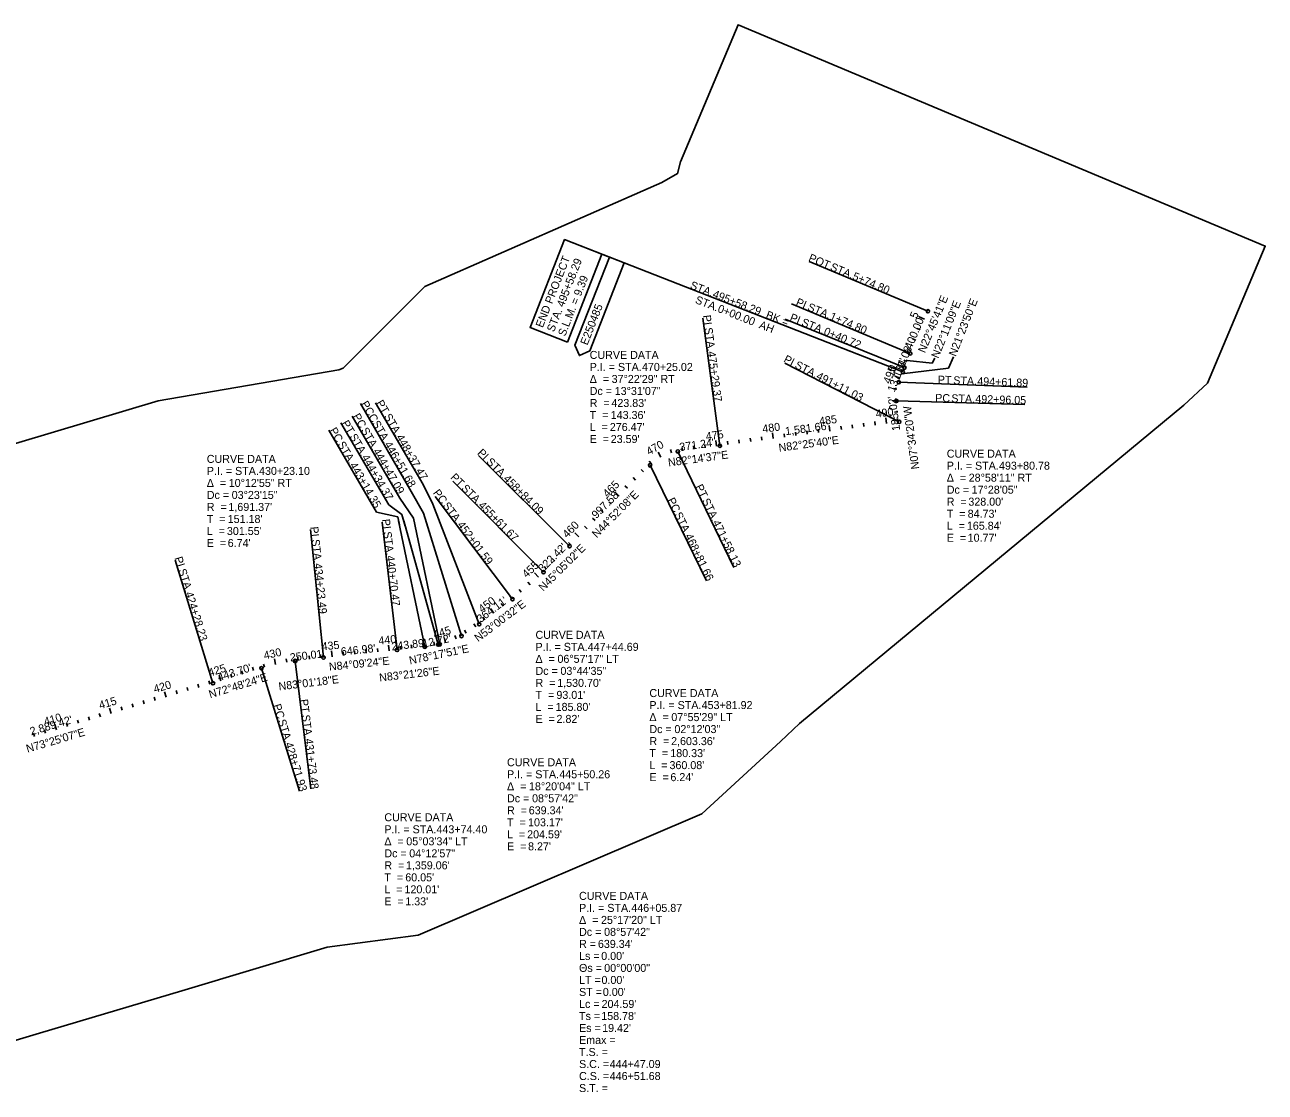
# Model space of a CAD drawing. Extents: x 187058 to 230449, y 263308 to 297406.
# Drawn here: x 219600 to 230449, y 288075 to 297406 of the extents above; entities that cross this region are included whole.
import ezdxf

# ---------------------------------------------------------------- set-up
doc = ezdxf.new("R2010")
doc.units = 0
for name, color, linetype in [('BR_X_Gen_Approach_Slab', 7, 'Continuous'), ('BR_X_SV_Deck_Top', 7, 'Continuous'), ('PV_X_Curb', 7, 'Continuous'), ('PV_X_Walk', 7, 'Continuous'), ('RD_X_GR_Lt', 7, 'Continuous'), ('SH_Named_Boundary', 7, 'Continuous')]:
    doc.layers.add(name, color=color, linetype=linetype)

msp = doc.modelspace()

# ---------------------------------------------------------------- linework, layer by layer
at = {"layer": 'BR_X_SV_Deck_Top'}
for p, q in [((227470, 294833), (227424, 294852)), ((227393, 294648), (227365, 294660)), ((227431, 294740), (227404, 294752)), ((227354, 294556), (227326, 294568)), ((227316, 294463), (227288, 294475)), ((227257, 294316), (227211, 294335)), ((227279, 294371), (227232, 294389)), ((227226, 294222), (227197, 294227)), ((227223, 294122), (227193, 294118)), ((227236, 294023), (227207, 294019)), ((226642, 293854), (226636, 293904)), ((226742, 293867), (226738, 293897)), ((226841, 293880), (226837, 293910)), ((226940, 293894), (226936, 293923)), ((227039, 293907), (227035, 293937)), ((227138, 293920), (227131, 293970)), ((227237, 293933), (227233, 293963)), ((225949, 293762), (225945, 293792)), ((226048, 293775), (226044, 293805)), ((226147, 293788), (226140, 293838)), ((226246, 293801), (226242, 293831)), ((226345, 293815), (226341, 293844)), ((226444, 293828), (226440, 293857)), ((226543, 293841), (226539, 293871)), ((225256, 293664), (225247, 293693)), ((225354, 293682), (225350, 293711)), ((225453, 293695), (225449, 293725)), ((225552, 293709), (225548, 293738)), ((225651, 293722), (225644, 293772)), ((225750, 293736), (225746, 293765)), ((225849, 293749), (225845, 293778)), ((225082, 293568), (225062, 293590)), ((225163, 293626), (225139, 293670)), ((225012, 293497), (224990, 293518)), ((224871, 293356), (224849, 293377)), ((224941, 293426), (224920, 293448)), ((224800, 293285), (224765, 293320)), ((224659, 293143), (224638, 293164)), ((224729, 293214), (224708, 293235)), ((224588, 293072), (224567, 293093)), ((224447, 292930), (224412, 292966)), ((224518, 293001), (224497, 293022)), ((224306, 292789), (224285, 292810)), ((224377, 292859), (224355, 292881)), ((224235, 292718), (224214, 292739)), ((224093, 292577), (224059, 292614)), ((224164, 292648), (224143, 292669)), ((224019, 292510), (223999, 292532)), ((223864, 292384), (223846, 292408)), ((223943, 292445), (223924, 292469)), ((223704, 292263), (223674, 292303)), ((223784, 292324), (223766, 292348)), ((223544, 292143), (223527, 292168)), ((223625, 292203), (223606, 292227)), ((223281, 292003), (223267, 292051)), ((223374, 292039), (223361, 292066)), ((223461, 292088), (223445, 292113)), ((222587, 291913), (222584, 291943)), ((222687, 291923), (222684, 291953)), ((222786, 291933), (222781, 291983)), ((222886, 291944), (222882, 291974)), ((222985, 291956), (222981, 291985)), ((223084, 291967), (223081, 291997)), ((223183, 291981), (223178, 292011)), ((221794, 291814), (221783, 291863)), ((221892, 291834), (221887, 291863)), ((221991, 291848), (221987, 291877)), ((222090, 291860), (222086, 291889)), ((222189, 291872), (222186, 291902)), ((222289, 291882), (222284, 291932)), ((222388, 291893), (222385, 291923)), ((222488, 291903), (222485, 291933)), ((221410, 291701), (221401, 291730)), ((221506, 291730), (221497, 291759)), ((221601, 291760), (221592, 291789)), ((221697, 291789), (221689, 291818)), ((221123, 291614), (221115, 291642)), ((221219, 291642), (221211, 291671)), ((221315, 291671), (221300, 291719)), ((220740, 291499), (220731, 291528)), ((220836, 291528), (220821, 291576)), ((220932, 291556), (220923, 291585)), ((221027, 291585), (221019, 291614)), ((220357, 291385), (220342, 291433)), ((220452, 291414), (220444, 291443)), ((220548, 291442), (220540, 291471)), ((220644, 291471), (220635, 291500)), ((219877, 291243), (219863, 291290)), ((219973, 291271), (219965, 291300)), ((220069, 291300), (220060, 291328)), ((220165, 291328), (220156, 291357)), ((220261, 291357), (220252, 291385)), ((219686, 291185), (219677, 291214)), ((219781, 291214), (219773, 291243))]:
    msp.add_line(p, q, dxfattribs=at)
at = {"layer": 'PV_X_Walk'}
for p, q in [((227279, 294371), (224322, 295529)), ((227499, 294902), (226462, 295337)), ((227279, 294371), (225952, 294891)), ((227344, 294533), (226307, 294968)), ((225680, 293726), (225532, 294841)), ((227294, 294409), (226252, 294833)), ((227248, 293935), (226248, 294449)), ((227319, 294471), (227536, 294448)), ((227536, 294448), (227559, 294493)), ((227679, 294405), (227724, 294503)), ((227272, 294354), (227679, 294405)), ((227244, 294281), (228368, 294239)), ((227224, 294118), (228348, 294088)), ((222535, 294094), (222979, 293326)), ((222668, 294102), (223085, 293387)), ((222365, 293926), (222784, 293209)), ((222463, 293986), (222881, 293269)), ((222258, 293863), (222675, 293146)), ((224365, 292848), (223568, 293642)), ((225312, 293676), (225801, 292663)), ((225069, 293555), (225562, 292544)), ((223085, 293387), (223168, 293215)), ((224137, 292620), (223343, 293417)), ((222881, 293269), (223001, 293092)), ((222979, 293326), (223086, 293137)), ((223865, 292385), (223189, 293283)), ((222675, 293146), (222862, 293106)), ((222784, 293209), (222899, 293126)), ((223420, 292063), (223086, 293137)), ((223575, 292166), (223168, 293215)), ((222856, 291941), (222726, 293058)), ((222862, 293106), (222877, 293036)), ((223099, 291969), (222870, 293070)), ((222899, 293126), (222928, 293022)), ((223217, 291988), (222914, 293071)), ((223229, 291990), (223001, 293092)), ((222213, 291875), (222098, 292994)), ((221246, 291650), (220914, 292725)), ((221965, 291844), (222101, 290728)), ((221670, 291781), (222003, 290707))]:
    msp.add_line(p, q, dxfattribs=at)
msp.add_lwpolyline([(224346, 294631), (224648, 295402), (224322, 295529), (224020, 294759)], close=True, dxfattribs=at)
msp.add_lwpolyline([(224713, 295376), (224411, 294606), (224451, 294515), (224541, 294555), (224843, 295325), (224648, 295402)], dxfattribs=at)
for centre in [(227499, 294902), (227344, 294533), (227279, 294371), (227294, 294409), (227244, 294281), (227224, 294118), (227248, 293935), (225312, 293676), (225680, 293726), (225069, 293555), (224365, 292848), (224137, 292620), (223865, 292385), (223575, 292166), (223420, 292063), (222856, 291941), (223099, 291969), (223217, 291988), (223229, 291990), (221965, 291844), (222213, 291875), (221670, 291781), (221246, 291650)]:
    msp.add_circle(centre, 15, dxfattribs=at)
at = {"layer": 'SH_Named_Boundary'}
msp.add_lwpolyline([(217055, 293010), (218483, 288219), (219728, 288590), (220974, 288961), (222245, 289342), (223041, 289446), (225522, 290507), (226211, 291141), (226377, 291297), (229737, 294082), (229946, 294273), (230449, 295471), (225839, 297406), (225336, 296207), (225310, 296106), (225171, 296027), (223099, 295119), (222384, 294404), (222347, 294389), (220767, 294119), (219547, 293753), (218301, 293382)], close=True, dxfattribs=at)

# ---------------------------------------------------------------- texts
at = {"layer": 'BR_X_Gen_Approach_Slab'}
for s, rotation, p in [("400.00'", 67.2385, (227356, 294564)), ("134.08'", 67.814, (227255, 294316)), ("137.11'", 68.6028, (227207, 294190)), ("185.02'", 97.5724, (227257, 293861)), ("1,581.66'", 7.5724, (226255, 293818)), ("371.24'", 7.7564, (225331, 293680)), ("997.58'", 45.1312, (224599, 293084)), ("322.42'", 44.9162, (224132, 292617)), ("364.11'", 36.9912, (223586, 292175)), ("12.72'", 11.7024, (223087, 291961)), ("250.01'", 6.9782, (221923, 291840)), ("646.98'", 5.8434, (222368, 291892)), ("243.89'", 6.6427, (222811, 291936)), ("443.70'", 17.1934, (221298, 291667)), ("2,889.42'", 16.5814, (219657, 291193))]:
    msp.add_text(s, height=70, rotation=rotation, dxfattribs=at).set_placement(p)
at = {"layer": 'BR_X_SV_Deck_Top'}
for s, rotation, p in [('5', 67.2385, (227402, 294832)), ('495', 68.6028, (227169, 294262)), ('0', 68.6028, (227210, 294368)), ('490', 7.5724, (227047, 293971)), ('480', 7.5724, (226056, 293839)), ('485', 7.5724, (226552, 293905)), ('475', 7.7564, (225561, 293773)), ('470', 29.1338, (225060, 293640)), ('465', 45.1312, (224697, 293270)), ('460', 45.1312, (224344, 292915)), ('455', 43.5588, (223990, 292566)), ('450', 36.9912, (223600, 292263)), ('440', 5.8434, (222697, 291987)), ('445', 16.444, (223184, 292040)), ('430', 12.8549, (221698, 291857)), ('435', 5.8434, (222200, 291936)), ('425', 17.1934, (221217, 291707)), ('420', 16.5814, (220738, 291564)), ('415', 16.5814, (220260, 291422)), ('410', 16.5814, (219779, 291279))]:
    msp.add_text(s, height=70, rotation=rotation, dxfattribs=at).set_placement(p)
at = {"layer": 'PV_X_Curb'}
for s, p in [('CURVE DATA', (224541, 294485)), ('P.I. = STA. ', (224541, 294380)), ('470+25.02', (224998, 294380)), ('Δ  = ', (224541, 294275)), ('37°22\'29" RT', (224733, 294275)), ('Dc = ', (224541, 294170)), ('13°31\'07"', (224760, 294170)), ('R  = ', (224541, 294065)), ("423.83'", (224731, 294065)), ('T  = ', (224541, 293960)), ("143.36'", (224725, 293960)), ('L  = ', (224541, 293855)), ("276.47'", (224717, 293855)), ('E  = ', (224541, 293750)), ("23.59'", (224725, 293750)), ('CURVE DATA', (227664, 293622)), ('CURVE DATA', (221192, 293576)), ('P.I. = STA. ', (227664, 293517)), ('493+80.78', (228121, 293517)), ('P.I. = STA. ', (221192, 293471)), ('430+23.10', (221649, 293471)), ('Δ  = ', (227664, 293412)), ('28°58\'11" RT', (227856, 293412)), ('Δ  = ', (221192, 293366)), ('10°12\'55" RT', (221384, 293366)), ('Dc = ', (227664, 293307)), ('17°28\'05"', (227882, 293307)), ('Dc = ', (221192, 293261)), ('03°23\'15"', (221410, 293261)), ('R  = ', (227664, 293202)), ("328.00'", (227853, 293202)), ('R  = ', (221192, 293156)), ("1,691.37'", (221381, 293156)), ('T  = ', (227664, 293097)), ("84.73'", (227847, 293097)), ('T  = ', (221192, 293051)), ("151.18'", (221375, 293051)), ('L  = ', (227664, 292992)), ("165.84'", (227840, 292992)), ('L  = ', (221192, 292946)), ("301.55'", (221368, 292946)), ('E  = ', (227664, 292887)), ("10.77'", (227847, 292887)), ('E  = ', (221192, 292841)), ("6.74'", (221375, 292841)), ('CURVE DATA', (224067, 292038)), ('P.I. = STA. ', (224067, 291933)), ('447+44.69', (224524, 291933)), ('Δ  = ', (224067, 291828)), ('06°57\'17" LT', (224259, 291828)), ('Dc = ', (224067, 291723)), ('03°44\'35"', (224285, 291723)), ('R  = ', (224067, 291618)), ("1,530.70'", (224257, 291618)), ('T  = ', (224067, 291513)), ("93.01'", (224250, 291513)), ('CURVE DATA', (225063, 291529)), ('L  = ', (224067, 291408)), ("185.80'", (224243, 291408)), ('P.I. = STA. ', (225063, 291424)), ('453+81.92', (225520, 291424)), ('E  = ', (224067, 291303)), ("2.82'", (224251, 291303)), ('Δ  = ', (225063, 291319)), ('07°55\'29" LT', (225255, 291319)), ('Dc = ', (225063, 291214)), ('02°12\'03"', (225282, 291214)), ('T  = ', (225063, 291004)), ('R  = ', (225063, 291109)), ("180.33'", (225246, 291004)), ("2,603.36'", (225253, 291109)), ('CURVE DATA', (223818, 290924)), ('L  = ', (225063, 290899)), ("360.08'", (225239, 290899)), ('P.I. = STA. ', (223818, 290819)), ('445+50.26', (224275, 290819)), ('E  = ', (225063, 290794)), ("6.24'", (225247, 290794)), ('Δ  = ', (223818, 290714)), ('18°20\'04" LT', (224010, 290714)), ('Dc = ', (223818, 290609)), ('08°57\'42"', (224037, 290609)), ('R  = ', (223818, 290504)), ("639.34'", (224008, 290504)), ('CURVE DATA', (222745, 290443)), ('T  = ', (223818, 290399)), ("103.17'", (224002, 290399)), ('P.I. = STA. ', (222745, 290338)), ('443+74.40', (223201, 290338)), ('L  = ', (223818, 290294)), ("204.59'", (223994, 290294)), ('Δ  = ', (222745, 290233)), ('05°03\'34" LT', (222937, 290233)), ('E  = ', (223818, 290189)), ("8.27'", (224002, 290189)), ('Dc = ', (222745, 290128)), ('04°12\'57"', (222963, 290128)), ('R  = ', (222745, 290023)), ("60.05'", (222928, 289918)), ("1,359.06'", (222934, 290023)), ('T  = ', (222745, 289918)), ('L  = ', (222745, 289813)), ("120.01'", (222921, 289813)), ('E  = ', (222745, 289708)), ("1.33'", (222928, 289708)), ('CURVE DATA', (224448, 289756)), ('P.I. = STA. ', (224448, 289651)), ('446+05.87', (224905, 289651)), ('Δ  = ', (224448, 289546)), ('25°17\'20" LT', (224640, 289546)), ('Dc = ', (224448, 289441)), ('08°57\'42"', (224667, 289441)), ('R = ', (224448, 289336)), ("639.34'", (224613, 289336)), ('Ls = ', (224448, 289231)), ("0.00'", (224642, 289231)), ('Θs = ', (224448, 289126)), ('00°00\'00"', (224668, 289126)), ('LT = ', (224448, 289021)), ("0.00'", (224644, 289021)), ('ST = ', (224448, 288916)), ("0.00'", (224656, 288916)), ('Lc = ', (224448, 288811)), ("204.59'", (224645, 288811)), ('Ts = ', (224448, 288706)), ("158.78'", (224642, 288706)), ('Es = ', (224448, 288601)), ("19.42'", (224650, 288601)), ('Emax = ', (224448, 288496)), ('T.S. = ', (224448, 288391)), ('S.C. = ', (224448, 288286)), ('444+47.09', (224716, 288286)), ('S.T. = ', (224448, 288076)), ('C.S. = ', (224448, 288181)), ('446+51.68', (224716, 288181))]:
    msp.add_text(s, height=70, dxfattribs=at).set_placement(p)
at = {"layer": 'PV_X_Walk'}
for s, rotation, p in [('END PROJECT', 68.6028, (224130, 294753)), ('STA. 495+58.29', 68.6028, (224228, 294715)), ('POT', 337.2385, (226449, 295343)), (' STA. ', 337.2385, (226615, 295274)), ('S.L.M. = 9.39', 68.6028, (224326, 294677)), ('5+74.80', 337.2385, (226833, 295182)), ('STA. ', 338.6028, (225413, 295103)), ('STA. ', 338.6028, (225458, 294975)), ('495+58.29', 338.6028, (225610, 295026)), ('PI', 337.2385, (226338, 294956)), ('E250485', 68.6028, (224521, 294600)), ('0+00.00', 338.6028, (225654, 294898)), (' BK =', 338.6028, (226051, 294853)), ('PI', 337.814, (226285, 294821)), (' STA. ', 337.2385, (226416, 294923)), ('1+74.80', 337.2385, (226634, 294832)), ('PI', 277.5724, (225530, 294865)), (' AH', 338.6028, (225992, 294766)), (' STA. ', 337.814, (226363, 294789)), (' STA. ', 277.5724, (225541, 294781)), ('0+40.72', 337.814, (226582, 294700)), ('475+29.37', 277.5724, (225572, 294547)), ('PI', 332.6788, (226231, 294461)), (' STA. ', 332.6788, (226306, 294422)), ('491+11.03', 332.6788, (226516, 294314)), ('PT', 357.9019, (227584, 294270)), (' STA. ', 357.9019, (227694, 294265)), ('494+61.89', 357.9019, (227930, 294257)), ('PCC', 300.1262, (222537, 294093)), ('PT', 300.2774, (222670, 294101)), ('PC', 358.4652, (227562, 294110)), (' STA. ', 358.4652, (227677, 294107)), ('492+96.05', 358.4652, (227913, 294101)), ('PC', 300.1804, (222466, 293984)), (' STA. ', 300.2774, (222726, 294005)), ('PT', 300.3142, (222368, 293924)), (' STA. ', 300.1262, (222623, 293944)), ('PC', 300.1948, (222262, 293861)), (' STA. ', 300.3142, (222424, 293829)), (' STA. ', 300.1804, (222524, 293884)), ('448+37.47', 300.2774, (222845, 293801)), (' STA. ', 300.1948, (222320, 293762)), ('444+47.09', 300.1804, (222642, 293680)), ('446+51.68', 300.1262, (222742, 293739)), ('PI', 315.1312, (223554, 293658)), ('444+34.37', 300.3142, (222543, 293625)), (' STA. ', 315.1312, (223614, 293598)), ('443+14.35', 300.1948, (222438, 293558)), ('PT', 314.9162, (223318, 293444)), (' STA. ', 314.9162, (223395, 293366)), ('458+84.09', 315.1312, (223781, 293431)), ('PT', 295.8195, (225462, 293369)), ('PC', 306.9912, (223167, 293313)), ('PC', 295.9671, (225218, 293252)), (' STA. ', 295.8195, (225510, 293270)), (' STA. ', 306.9912, (223236, 293222)), ('455+61.67', 314.9162, (223562, 293199)), (' STA. ', 295.9671, (225268, 293149)), ('PI', 276.6427, (222724, 293082)), ('452+01.59', 306.9912, (223378, 293033)), ('471+58.13', 295.8195, (225613, 293057)), ('PI', 275.8434, (222097, 293016)), (' STA. ', 276.6427, (222734, 292998)), ('468+81.66', 295.9671, (225372, 292937)), (' STA. ', 275.8434, (222106, 292931)), ('PI', 287.1934, (220909, 292745)), ('440+70.47', 276.6427, (222762, 292763)), (' STA. ', 287.1934, (220934, 292664)), ('434+23.49', 275.8434, (222130, 292696)), ('424+28.23', 287.1934, (221003, 292438)), ('PT', 276.9782, (222007, 291507)), ('PC', 287.1934, (221771, 291457)), (' STA. ', 287.1934, (221805, 291348)), (' STA. ', 276.9782, (222020, 291397)), ('428+71.93', 287.1934, (221875, 291122)), ('431+73.48', 276.9782, (222049, 291163))]:
    msp.add_text(s, height=70, rotation=rotation, dxfattribs=at).set_placement(p)
at = {"layer": 'RD_X_GR_Lt'}
for s, rotation, p in [('N22°45\'41"E', 67.2385, (227473, 294532)), ('N22°11\'09"E', 67.814, (227590, 294485)), ('N21°23\'50"E', 68.6028, (227743, 294501)), ('N07°34\'20"W', 97.5724, (227424, 293525)), ('N82°25\'40"E', 7.5724, (226198, 293674)), ('N82°14\'37"E', 7.7564, (225231, 293544)), ('N44°52\'08"E', 45.1312, (224602, 292916)), ('N45°05\'02"E', 44.9162, (224135, 292449)), ('N53°00\'32"E', 36.9912, (223565, 292008)), ('N78°17\'51"E', 11.7024, (222969, 291814)), ('N84°09\'24"E', 5.8434, (222264, 291759)), ('N72°48\'24"E', 17.1934, (221222, 291517)), ('N83°21\'26"E', 6.6427, (222704, 291664)), ('N83°01\'18"E', 6.9782, (221824, 291587)), ('N73°25\'07"E', 16.5814, (219624, 291042))]:
    msp.add_text(s, height=70, rotation=rotation, dxfattribs=at).set_placement(p)

doc.saveas('drawing.dxf')
